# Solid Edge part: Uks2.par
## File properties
Author: Türk
Template: iso part.par
Last saved by: Türk
Revision: 4
Application: Solid Edge
Accuracy: 0,990
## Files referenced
..\..\Raam\Raami koostu.asm
=C:\Kristjan\Solid Edge ST4\Auto projekt\Raam\Raami koostu.asm
uto projekt\Kere\Uks2.par
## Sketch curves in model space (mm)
line (-754.9125, 2100, 150) -> (-754.9125, 1100, 150)
line (-637.0219, 1100, 549.8297) -> (-650, 1100, 450)
line (-591.886, 1100, 731.4928) -> (-636.9584, 1100, 550.1667)
arc centre (-349.269, 1100, 671.1853) radius 250 from (-377.4735, 1100, 919.5892) through (-519.499, 1100, 854.2747) to (-591.886, 1100, 731.4928)
line (-100, 1100, 951.0944) -> (-377.4735, 1100, 919.5892)
spline (-754.9125, 1100, 144.8721) -> (-732.4046, 1100, -13.8518) -> (-650, 1100, -150)
spline (-646.9489, 1100, 450.1987) -> (-743.8572, 1100, 319.9786) -> (-754.9125, 1100, 144.8721)
line (-100, 1062.3168, 916.0944) -> (-100, 1680.2708, 916.0944)
line (-100, 1097, 951.0944) -> (-100, 1675.537, 951.0944)
spline (-100, 1680.2708, 950.9341) -> (-100, 1895.5951, 934.0915) -> (-100, 2100, 877.639)
line (-100, 1680.2708, 929.0944) -> (-100, 1100, 929.0944)
line (-100, 1680.2708, 915.8853) -> (-100, 1680.2708, 929.0944)
spline (-100, 2100, 838.6626) -> (-100, 1901.057, 898.24) -> (-100, 1680.2708, 915.8853)
arc centre (-46.4058, 2100, -2636.1123) radius 3513.4177 from (-111.9955, 2100, 876.6931) through (-105.9978, 2100, 876.8) to (-100, 2100, 876.8966)
spline (-133.648, 2100, 876.1609) -> (-122.8255, 2100, 876.4629) -> (-111.9955, 2100, 876.6931)
line (-354.2278, 2100, 868.8643) -> (-133.648, 2100, 876.1609)
spline (-569.13, 2100, 800.4559) -> (-477.8028, 2100, 851.5783) -> (-372.4728, 2100, 867.6459)
spline (-372.4728, 2100, 867.6459) -> (-363.3186, 2100, 868.305) -> (-354.158, 2100, 868.8666)
line (-650, 2100, 550) -> (-595.9573, 2100, 739.1494)
arc centre (-355.5763, 2100, 670.4691) radius 250 from (-595.9573, 2100, 739.1494) through (-584.6022, 2100, 770.7045) to (-569.1259, 2100, 800.4559)
spline (-754.9125, 2100, 144.8721) -> (-732.4046, 2100, -13.8518) -> (-650, 2100, -150)
spline (-741.7948, 2100, 332.8619) -> (-752.2491, 2100, 239.1331) -> (-754.9125, 2100, 144.8721)
line (-734.6782, 2100, 372.6364) -> (-741.7948, 2100, 332.8619)
spline (-646.0712, 2100, 552.8307) -> (-700.1808, 2100, 486.6065) -> (-734.6782, 2100, 372.6364)
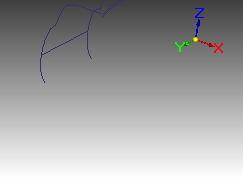
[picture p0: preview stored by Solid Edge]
